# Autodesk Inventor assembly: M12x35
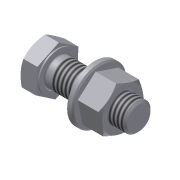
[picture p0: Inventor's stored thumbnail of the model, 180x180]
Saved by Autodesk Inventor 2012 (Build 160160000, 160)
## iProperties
Company: CAD-Verlag
Created: 2004-12
Part Number: M12x35
Document SubType Name: Assembly
Designer: jukr
Manufacturer: Standard
Standards Organization: Custom
Author: Jürgen Kronas
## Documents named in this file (4)
- C:\DemoDaten2012\CAD Daten\Daten Vault 2012 Inventor\Kapitel 4\Anschlag\Normteile\M12x35.iam
- C:\DemoDaten2012\CAD Daten\Daten Vault 2012 Inventor\Kapitel 4\Anschlag\Normteile\I4032000YBW6B_MIR.ipt
- C:\DemoDaten2012\CAD Daten\Daten Vault 2012 Inventor\Kapitel 4\Anschlag\Normteile\I4017A000Q9FLB_MIR.ipt
- C:\DemoDaten2012\CAD Daten\Daten Vault 2012 Inventor\Kapitel 4\Anschlag\Normteile\D125_2000RI1XB_MIR.ipt
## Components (3 placed, 3 different names)
1. I4032000YBW6B_MIR:1
2. I4017A000Q9FLB_MIR:1
3. D125_2000RI1XB_MIR:1
